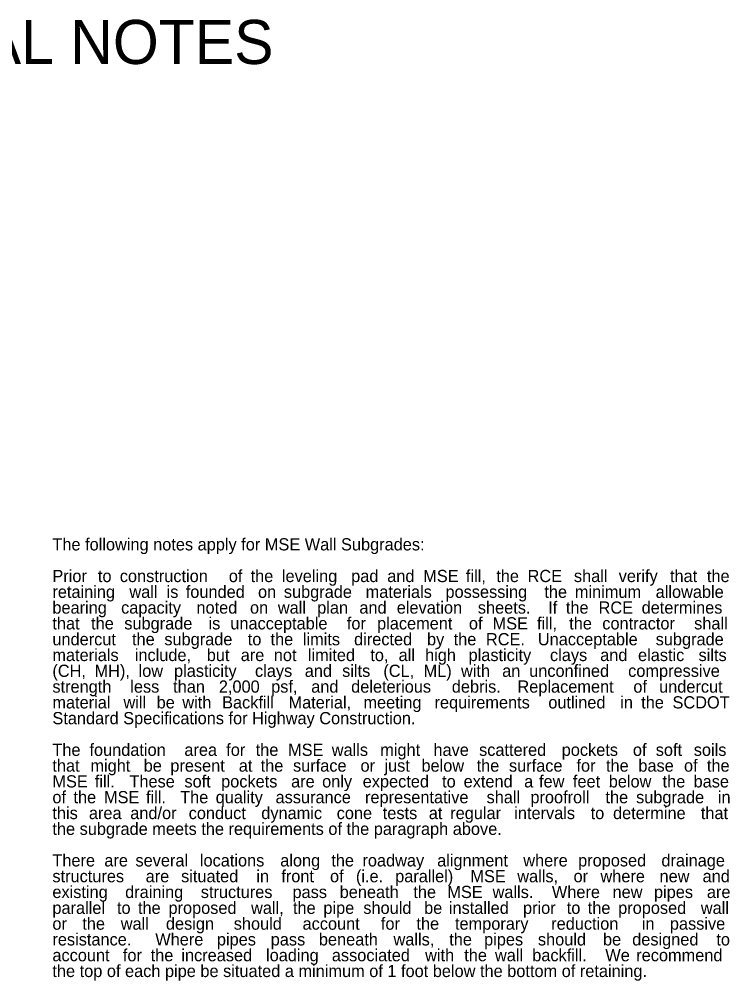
# Model space of a CAD drawing. Extents: x 4804 to 5434, y 4929 to 5221.
# Drawn here: x 5183.2 to 5263.7, y 5106.2 to 5215.2 of the extents above; entities that cross this region are included whole.
import ezdxf

# ---------------------------------------------------------------- set-up
doc = ezdxf.new("R2010")
doc.units = 0
doc.layers.add('RD_TX_RoadID', color=7, linetype='Continuous')

msp = doc.modelspace()

# ---------------------------------------------------------------- texts
at = {"layer": 'RD_TX_RoadID'}
for s, height, p in [('GEOTECHNICAL NOTES', 5, (5134.37, 5210.16)), ('The following notes apply for MSE Wall Subgrades:', 1.3845, (5186.95, 5155)), ('Prior ', 1.384, (5186.95, 5151.41)), ('to ', 1.384, (5192.11, 5151.41)), ('construction ', 1.3845, (5194.59, 5151.41)), ('of ', 1.384, (5206.95, 5151.41)), ('the ', 1.384, (5209.42, 5151.41)), ('leveling ', 1.384, (5212.97, 5151.41)), ('pad ', 1.384, (5220.82, 5151.41)), ('and ', 1.384, (5224.91, 5151.41)), ('MSE ', 1.384, (5228.99, 5151.41)), ('fill, ', 1.384, (5233.83, 5151.41)), ('the ', 1.384, (5237.27, 5151.41)), ('RCE ', 1.384, (5240.82, 5151.41)), (' shall ', 1.384, (5245.56, 5151.41)), ('verify ', 1.384, (5251.15, 5151.41)), ('that ', 1.384, (5256.96, 5151.41)), ('the ', 1.384, (5261.15, 5151.41)), ('retaining ', 1.384, (5186.95, 5149.62)), ('wall ', 1.384, (5195.68, 5149.62)), ('is ', 1.384, (5199.9, 5149.62)), ('founded ', 1.384, (5202.07, 5149.62)), ('subgrade ', 1.384, (5213.19, 5149.62)), ('materials ', 1.384, (5222.46, 5149.62)), ('possessing ', 1.3845, (5231.51, 5149.62)), ('the ', 1.384, (5242.72, 5149.62)), ('minimum ', 1.384, (5246.18, 5149.62)), ('allowable ', 1.384, (5255.34, 5149.62)), ('on ', 1.384, (5210.26, 5149.62)), ('bearing ', 1.384, (5186.95, 5147.83)), ('capacity ', 1.384, (5194.74, 5147.83)), ('noted ', 1.384, (5203.28, 5147.83)), ('on ', 1.384, (5209.35, 5147.83)), ('wall ', 1.384, (5212.51, 5147.83)), ('plan ', 1.384, (5216.97, 5147.83)), ('and ', 1.384, (5221.75, 5147.83)), ('elevation ', 1.384, (5225.99, 5147.83)), ('sheets. ', 1.384, (5235.18, 5147.83)), (' If ', 1.384, (5242.64, 5147.83)), ('the ', 1.384, (5245.16, 5147.83)), ('RCE ', 1.384, (5248.87, 5147.83)), ('determines ', 1.3845, (5253.75, 5147.83)), ('that ', 1.384, (5186.95, 5146.04)), ('the ', 1.384, (5191.34, 5146.04)), ('subgrade ', 1.384, (5195.1, 5146.04)), ('is ', 1.384, (5204.65, 5146.04)), ('unacceptable ', 1.3845, (5207.12, 5146.04)), ('for ', 1.384, (5220.33, 5146.04)), ('placement ', 1.384, (5223.76, 5146.04)), ('of ', 1.384, (5234.17, 5146.04)), ('MSE ', 1.384, (5236.85, 5146.04)), ('fill, ', 1.384, (5241.89, 5146.04)), ('the ', 1.384, (5245.54, 5146.04)), ('contractor ', 1.3845, (5249.29, 5146.04)), ('shall ', 1.384, (5259.7, 5146.04)), ('undercut ', 1.384, (5186.95, 5144.24)), ('the ', 1.384, (5195.98, 5144.24)), ('subgrade ', 1.384, (5199.64, 5144.24)), ('the ', 1.384, (5211.68, 5144.24)), ('limits ', 1.384, (5215.34, 5144.24)), ('directed ', 1.384, (5221.15, 5144.24)), ('by ', 1.384, (5229.42, 5144.24)), ('the ', 1.384, (5232.44, 5144.24)), ('RCE. ', 1.384, (5236.1, 5144.24)), (' Unacceptable ', 1.3845, (5241.47, 5144.24)), ('subgrade ', 1.384, (5255.34, 5144.24)), ('to ', 1.384, (5209.1, 5144.24)), ('materials ', 1.384, (5186.95, 5142.45)), ('include, ', 1.384, (5196.29, 5142.45)), ('but ', 1.384, (5204.45, 5142.45)), ('are ', 1.384, (5208.3, 5142.45)), ('not ', 1.384, (5212.05, 5142.45)), ('limited ', 1.384, (5215.91, 5142.45)), ('to, ', 1.384, (5222.99, 5142.45)), ('all ', 1.384, (5226.2, 5142.45)), ('high ', 1.384, (5229.2, 5142.45)), ('plasticity ', 1.3845, (5234.13, 5142.45)), ('clays ', 1.384, (5243.36, 5142.45)), ('and ', 1.384, (5249.05, 5142.45)), ('elastic ', 1.384, (5253.34, 5142.45)), ('silts ', 1.384, (5260.2, 5142.45)), ('(CH, ', 1.384, (5186.95, 5140.66)), ('MH), ', 1.384, (5191.73, 5140.66)), ('low ', 1.384, (5196.72, 5140.66)), ('plasticity ', 1.3845, (5200.74, 5140.66)), ('clays ', 1.384, (5209.92, 5140.66)), ('and ', 1.384, (5215.56, 5140.66)), ('silts ', 1.384, (5219.8, 5140.66)), ('(CL, ', 1.384, (5224.47, 5140.66)), ('ML) ', 1.384, (5229.03, 5140.66)), ('with ', 1.384, (5233.27, 5140.66)), ('an ', 1.384, (5237.94, 5140.66)), ('unconfined ', 1.3845, (5241, 5140.66)), ('compressive ', 1.3845, (5252.22, 5140.66)), ('strength ', 1.384, (5186.95, 5138.87)), ('less ', 1.384, (5195.78, 5138.87)), ('than ', 1.384, (5200.64, 5138.87)), ('2,000 ', 1.384, (5205.82, 5138.87)), ('psf, ', 1.384, (5211.75, 5138.87)), ('and ', 1.384, (5216.29, 5138.87)), ('deleterious ', 1.3845, (5220.82, 5138.87)), ('debris. ', 1.384, (5232.23, 5138.87)), ('Replacement ', 1.3845, (5239.67, 5138.87)), ('of ', 1.384, (5252.81, 5138.87)), ('undercut ', 1.384, (5255.73, 5138.87)), ('material ', 1.384, (5186.95, 5137.08)), ('will ', 1.384, (5195.01, 5137.08)), ('be ', 1.384, (5198.77, 5137.08)), ('with ', 1.384, (5201.68, 5137.08)), ('Backfill ', 1.384, (5206.19, 5137.08)), ('Material, ', 1.384, (5213.72, 5137.08)), ('meeting ', 1.384, (5222.21, 5137.08)), ('requirements ', 1.3845, (5230.27, 5137.08)), ('outlined ', 1.384, (5243.17, 5137.08)), ('in ', 1.384, (5251.33, 5137.08)), ('the ', 1.384, (5253.7, 5137.08)), ('SCDOT ', 1.384, (5257.25, 5137.08)), ('Standard Specifications for Highway Construction.', 1.3845, (5186.95, 5135.29)), ('The ', 1.384, (5186.95, 5131.7)), ('foundation ', 1.3845, (5191.15, 5131.7)), ('area ', 1.384, (5201.91, 5131.7)), ('for ', 1.384, (5206.66, 5131.7)), ('the ', 1.384, (5210, 5131.7)), ('MSE ', 1.384, (5213.67, 5131.7)), ('walls ', 1.384, (5218.62, 5131.7)), ('might ', 1.384, (5224.12, 5131.7)), ('have ', 1.384, (5230.15, 5131.7)), ('scattered ', 1.384, (5235.32, 5131.7)), ('pockets ', 1.384, (5244.69, 5131.7)), ('of ', 1.384, (5252.76, 5131.7)), ('soft ', 1.384, (5255.35, 5131.7)), ('soils ', 1.384, (5259.66, 5131.7)), ('that ', 1.384, (5186.95, 5129.91)), ('might ', 1.384, (5191.26, 5129.91)), ('be ', 1.384, (5197.3, 5129.91)), ('present ', 1.384, (5200.32, 5129.91)), ('at ', 1.384, (5208.08, 5129.91)), ('the ', 1.384, (5210.56, 5129.91)), ('surface ', 1.384, (5214.23, 5129.91)), ('or ', 1.384, (5221.88, 5129.91)), ('just ', 1.384, (5224.59, 5129.91)), ('below ', 1.384, (5228.79, 5129.91)), ('the ', 1.384, (5235.04, 5129.91)), ('surface ', 1.384, (5238.71, 5129.91)), ('for ', 1.384, (5246.36, 5129.91)), ('the ', 1.384, (5249.71, 5129.91)), ('base ', 1.384, (5253.38, 5129.91)), ('of ', 1.384, (5258.55, 5129.91)), ('the ', 1.384, (5261.15, 5129.91)), ('MSE ', 1.384, (5186.95, 5128.12)), ('fill. ', 1.384, (5191.76, 5128.12)), (' These ', 1.384, (5195.17, 5128.12)), ('soft ', 1.384, (5201.92, 5128.12)), ('pockets ', 1.384, (5206.08, 5128.12)), ('are ', 1.384, (5214.01, 5128.12)), ('only ', 1.384, (5217.53, 5128.12)), ('expected ', 1.384, (5222.13, 5128.12)), ('to ', 1.384, (5231.13, 5128.12)), ('extend ', 1.384, (5233.57, 5128.12)), ('a ', 1.384, (5240.43, 5128.12)), ('few ', 1.384, (5242.12, 5128.12)), ('feet ', 1.384, (5245.96, 5128.12)), ('below ', 1.384, (5250.02, 5128.12)), ('the ', 1.384, (5256.12, 5128.12)), ('base ', 1.384, (5259.64, 5128.12)), ('of ', 1.384, (5186.95, 5126.33)), ('the ', 1.384, (5189.34, 5126.33)), ('MSE ', 1.384, (5192.8, 5126.33)), ('fill. ', 1.384, (5197.56, 5126.33)), (' The ', 1.384, (5200.92, 5126.33)), ('quality ', 1.384, (5205.46, 5126.33)), ('assurance ', 1.384, (5212.25, 5126.33)), ('representative ', 1.3845, (5222.39, 5126.33)), ('shall ', 1.384, (5236.17, 5126.33)), ('proofroll ', 1.384, (5241.14, 5126.33)), ('the ', 1.384, (5249.65, 5126.33)), ('subgrade ', 1.384, (5253.12, 5126.33)), ('in ', 1.384, (5262.39, 5126.33)), ('this ', 1.384, (5186.95, 5124.53)), ('and/or ', 1.384, (5195.78, 5124.53)), ('conduct ', 1.384, (5202.4, 5124.53)), ('dynamic ', 1.384, (5210.63, 5124.53)), ('regular ', 1.384, (5232.05, 5124.53)), ('intervals ', 1.384, (5239.31, 5124.53)), ('determine ', 1.384, (5250.51, 5124.53)), ('that ', 1.384, (5260.46, 5124.53)), ('area ', 1.384, (5191.09, 5124.53)), ('cone ', 1.384, (5219.18, 5124.53)), ('tests ', 1.384, (5224.4, 5124.53)), ('at ', 1.384, (5229.62, 5124.53)), ('to ', 1.384, (5247.97, 5124.53)), ('the subgrade meets the requirements of the paragraph above. ', 1.3845, (5186.95, 5122.74)), ('There ', 1.384, (5186.95, 5119.16)), ('several ', 1.384, (5196.37, 5119.16)), ('locations ', 1.384, (5203.67, 5119.16)), ('along ', 1.384, (5212.78, 5119.16)), ('the ', 1.384, (5218.57, 5119.16)), ('roadway ', 1.384, (5222.1, 5119.16)), ('alignment ', 1.384, (5230.57, 5119.16)), ('where ', 1.384, (5240.33, 5119.16)), ('proposed ', 1.384, (5246.55, 5119.16)), ('drainage ', 1.384, (5255.99, 5119.16)), ('are ', 1.384, (5192.84, 5119.16)), ('structures ', 1.3845, (5186.95, 5117.37)), ('are ', 1.384, (5197.52, 5117.37)), ('situated ', 1.384, (5201.54, 5117.37)), ('in ', 1.384, (5210.07, 5117.37)), ('front ', 1.384, (5212.9, 5117.37)), ('of ', 1.384, (5218.42, 5117.37)), ('(i.e. ', 1.384, (5221.36, 5117.37)), ('parallel) ', 1.384, (5225.81, 5117.37)), ('MSE ', 1.384, (5234.34, 5117.37)), ('walls, ', 1.384, (5239.65, 5117.37)), ('or ', 1.384, (5246.03, 5117.37)), ('where ', 1.384, (5249.08, 5117.37)), ('new ', 1.384, (5255.78, 5117.37)), ('and ', 1.384, (5260.66, 5117.37)), ('existing ', 1.384, (5186.95, 5115.58)), ('draining ', 1.384, (5195.2, 5115.58)), ('structures ', 1.3845, (5203.77, 5115.58)), ('pass ', 1.384, (5214.17, 5115.58)), ('beneath ', 1.384, (5219.52, 5115.58)), ('the ', 1.384, (5227.87, 5115.58)), ('MSE ', 1.384, (5231.72, 5115.58)), ('walls. ', 1.384, (5236.85, 5115.58)), (' Where ', 1.384, (5243.06, 5115.58)), ('new ', 1.384, (5250.45, 5115.58)), ('pipes ', 1.384, (5255.15, 5115.58)), ('are ', 1.384, (5261.15, 5115.58)), ('parallel ', 1.384, (5186.95, 5113.78)), ('to ', 1.384, (5194.27, 5113.78)), ('the ', 1.384, (5196.65, 5113.78)), ('proposed ', 1.384, (5200.11, 5113.78)), ('wall, ', 1.384, (5209.47, 5113.78)), ('the ', 1.384, (5214.22, 5113.78)), ('pipe ', 1.384, (5217.67, 5113.78)), ('should ', 1.384, (5222.2, 5113.78)), ('be ', 1.384, (5229.09, 5113.78)), ('installed ', 1.384, (5231.9, 5113.78)), ('prior ', 1.384, (5240.3, 5113.78)), ('to ', 1.384, (5245.26, 5113.78)), ('the ', 1.384, (5247.64, 5113.78)), ('proposed ', 1.384, (5251.09, 5113.78)), ('wall ', 1.384, (5260.46, 5113.78)), ('or ', 1.384, (5186.95, 5111.99)), ('the ', 1.384, (5190.34, 5111.99)), ('wall ', 1.384, (5194.7, 5111.99)), ('design ', 1.384, (5199.82, 5111.99)), ('should ', 1.384, (5207.51, 5111.99)), ('account ', 1.384, (5215.31, 5111.99)), ('for ', 1.384, (5224.19, 5111.99)), ('the ', 1.384, (5228.22, 5111.99)), ('temporary ', 1.384, (5232.59, 5111.99)), ('reduction ', 1.384, (5243.5, 5111.99)), ('in ', 1.384, (5253.77, 5111.99)), ('passive ', 1.384, (5256.95, 5111.99)), ('resistance. ', 1.3845, (5186.95, 5110.2)), (' Where ', 1.384, (5198.1, 5110.2)), ('pipes ', 1.384, (5205.6, 5110.2)), ('pass ', 1.384, (5211.7, 5110.2)), ('beneath ', 1.384, (5217.16, 5110.2)), ('walls, ', 1.384, (5225.62, 5110.2)), ('the ', 1.384, (5231.94, 5110.2)), ('pipes ', 1.384, (5235.89, 5110.2)), ('should ', 1.384, (5241.99, 5110.2)), ('be ', 1.384, (5249.37, 5110.2)), ('designed ', 1.384, (5252.68, 5110.2)), ('to ', 1.384, (5262.22, 5110.2)), ('account ', 1.384, (5186.95, 5108.41)), ('for ', 1.384, (5194.94, 5108.41)), ('the ', 1.384, (5198.09, 5108.41)), ('increased ', 1.384, (5201.57, 5108.41)), ('loading ', 1.384, (5211.17, 5108.41)), ('associated ', 1.3845, (5218.63, 5108.41)), ('with ', 1.384, (5229.2, 5108.41)), ('the ', 1.384, (5233.64, 5108.41)), ('wall ', 1.384, (5237.12, 5108.41)), ('backfill. ', 1.384, (5241.35, 5108.41)), (' We ', 1.384, (5249.12, 5108.41)), ('recommend ', 1.384, (5253.14, 5108.41)), ('the top of each pipe be situated a minimum of 1 foot below the bottom of retaining.', 1.3845, (5186.95, 5106.62))]:
    msp.add_text(s, height=height, dxfattribs=at).set_placement(p)

doc.saveas('drawing.dxf')
